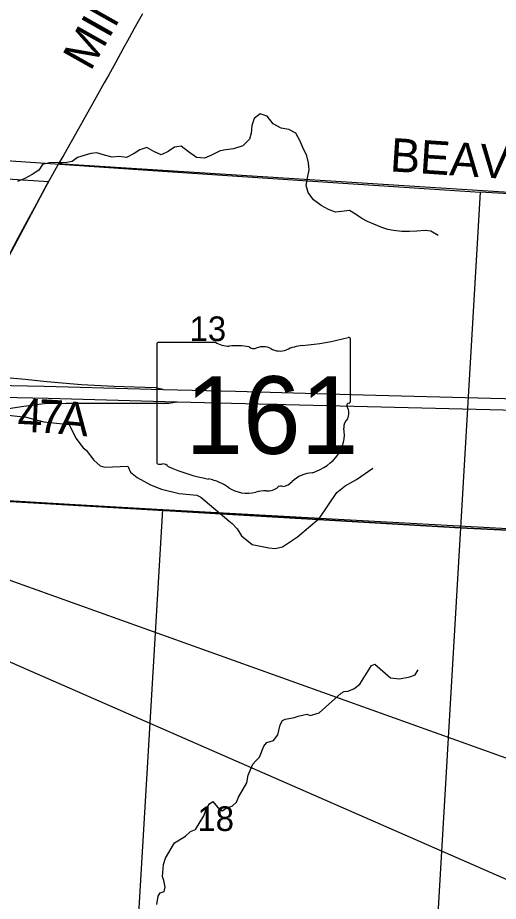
# Model space of a CAD drawing. Extents: x 0 to 91.3, y -0.7 to 22.
# Drawn here: x 7.164 to 7.981, y 16.725 to 18.226 of the extents above; entities that cross this region are included whole.
import ezdxf

# ---------------------------------------------------------------- set-up
doc = ezdxf.new("R2010")
doc.units = 0
for name, color, linetype in [('GM_X_Corporation', 7, 'Continuous'), ('GM_X_County_Road', 7, 'Continuous'), ('GM_X_County_Road_Text', 7, 'Continuous'), ('GM_X_Interchange_Ramps', 7, 'Continuous'), ('GM_X_Major_River', 7, 'Continuous'), ('GM_X_Minor_River', 7, 'Continuous'), ('GM_X_Section_Text', 7, 'Continuous'), ('GM_X_State_Location', 7, 'Continuous'), ('GM_X_State_Route', 7, 'Continuous'), ('GM_X_State_Shield', 7, 'Continuous'), ('GM_X_Township_Road', 7, 'Continuous'), ('GM_X_Township_Road_Text', 7, 'Continuous'), ('SH_Text', 7, 'Continuous')]:
    doc.layers.add(name, color=color, linetype=linetype)

msp = doc.modelspace()

# ---------------------------------------------------------------- linework, layer by layer
at = {"layer": 'GM_X_Corporation'}
for points in [[(6.9448, 17.9966), (7.4187, 17.9645), (7.6912, 17.9463), (7.9506, 17.929), (7.9172, 17.3589), (6.9092, 17.4181)], [(8.9, 17.3103), (8.9, 17.8759), (8.8451, 17.8791), (8.4604, 17.9014), (8.0797, 17.922), (7.9506, 17.929), (7.9172, 17.3589)], [(6.9092, 17.4181), (7.9172, 17.3589), (7.8571, 16.3365), (6.8465, 16.3992)], [(8.9, 16.8754), (8.9, 17.3103), (7.9172, 17.3589), (7.8571, 16.3365), (8.8671, 16.2825)]]:
    msp.add_lwpolyline(points, close=True, dxfattribs=at)
msp.add_lwpolyline([(7.1102, 17.7478), (7.2165, 17.9469), (7.0938, 17.9548)], dxfattribs=at)
at = {"layer": 'GM_X_County_Road'}
for points in [[(7.3765, 18.2324), (7.3618, 18.2063), (7.354, 18.1916), (7.3431, 18.1719), (7.3307, 18.149), (7.3193, 18.1287), (7.3114, 18.1149), (7.2973, 18.0895), (7.2865, 18.0703), (7.2786, 18.0559), (7.2678, 18.0368), (7.2549, 18.0145), (7.2424, 17.9927), (7.2341, 17.9783), (7.2155, 17.9453), (7.2146, 17.9435)], [(7.2146, 17.9435), (7.2058, 17.9273), (7.196, 17.9094), (7.1765, 17.8732)], [(7.1765, 17.8732), (7.176, 17.8723), (7.1653, 17.8521), (7.1576, 17.8379), (7.1385, 17.8015), (7.1283, 17.7822), (7.1245, 17.7751)], [(7.0214, 17.4132), (7.1002, 17.4084), (7.2619, 17.3986), (7.4112, 17.39), (8.3263, 17.3397), (8.5262, 17.3288), (8.8216, 17.3124), (8.9, 17.3095)]]:
    msp.add_lwpolyline(points, dxfattribs=at)
at = {"layer": 'GM_X_Interchange_Ramps'}
for points in [[(7.4118, 17.5942), (7.3985, 17.5971), (7.3279, 17.599), (7.2725, 17.6018), (7.2137, 17.6069), (7.1768, 17.611), (7.0497, 17.6225)], [(7.0157, 17.5554), (7.0325, 17.5545), (7.058, 17.5516), (7.082, 17.5518), (7.103, 17.5537), (7.127, 17.5576), (7.1523, 17.5623), (7.1706, 17.5654), (7.1955, 17.5687), (7.2094, 17.5701), (7.2466, 17.5708), (7.2877, 17.571), (7.4209, 17.5708), (7.4356, 17.5734)]]:
    msp.add_lwpolyline(points, dxfattribs=at)
at = {"layer": 'GM_X_Major_River'}
msp.add_lwpolyline([(7.879, 17.8559), (7.8665, 17.8632), (7.857, 17.864), (7.843, 17.8633), (7.8305, 17.8626), (7.8172, 17.8623), (7.8032, 17.8642), (7.7933, 17.8658), (7.7835, 17.8692), (7.7695, 17.875), (7.7589, 17.8792), (7.749, 17.8845), (7.7384, 17.8921), (7.7282, 17.8979), (7.7146, 17.8964), (7.7047, 17.8953), (7.6926, 17.8999), (7.6801, 17.9064), (7.6669, 17.9163), (7.6578, 17.9285), (7.6545, 17.9406), (7.6568, 17.9535), (7.6599, 17.9671), (7.6584, 17.9789), (7.6558, 17.991), (7.649, 18.0051), (7.6438, 18.0172), (7.637, 18.0294), (7.6253, 18.0355), (7.612, 18.0382), (7.5988, 18.0451), (7.5882, 18.0584), (7.5765, 18.0626), (7.5662, 18.0543), (7.562, 18.0426), (7.5612, 18.0297), (7.5581, 18.0195), (7.5467, 18.0078), (7.5311, 18.0029), (7.5182, 18.001), (7.5084, 17.9996), (7.4939, 17.992), (7.4818, 17.9868), (7.4681, 17.9884), (7.4545, 17.9975), (7.442, 18.0074), (7.431, 18.0056), (7.42, 17.9984), (7.4079, 17.9928), (7.3954, 17.9985), (7.3836, 18.0054), (7.3719, 18.0012), (7.362, 17.9952), (7.3491, 17.9884), (7.337, 17.9896), (7.3248, 17.9889), (7.3119, 17.992), (7.2987, 17.9962), (7.2885, 17.9951), (7.279, 17.9921), (7.2661, 17.988), (7.2566, 17.9816), (7.2448, 17.979), (7.2315, 17.9798), (7.2183, 17.9791), (7.2065, 17.9765), (7.2004, 17.9667), (7.189, 17.9595), (7.1765, 17.9527), (7.1639, 17.9475)], dxfattribs=at)
at = {"layer": 'GM_X_Minor_River'}
for points in [[(7.1379, 17.5517), (7.1784, 17.5473), (7.2087, 17.5392), (7.2519, 17.5347), (7.2628, 17.5112), (7.2756, 17.4951), (7.2808, 17.4909), (7.2936, 17.4738), (7.3046, 17.4643), (7.3125, 17.4623), (7.3516, 17.464), (7.3561, 17.4537), (7.3674, 17.4445), (7.3901, 17.4323), (7.4086, 17.4246), (7.4385, 17.4176), (7.4688, 17.4144), (7.4753, 17.4113), (7.5232, 17.3712), (7.5288, 17.3662), (7.5371, 17.3575), (7.5446, 17.3453), (7.5628, 17.3308), (7.5912, 17.3249), (7.6018, 17.3241), (7.6143, 17.327), (7.6398, 17.3436), (7.6771, 17.3756), (7.7069, 17.4194), (7.721, 17.4307), (7.74, 17.4412), (7.7678, 17.4604)], [(7.5828, 16.9882), (7.5878, 16.9943), (7.5992, 16.998), (7.6064, 17.0074), (7.6107, 17.0245), (7.6142, 17.0317), (7.6191, 17.0343), (7.6347, 17.0368), (7.6411, 17.0391), (7.6555, 17.0428), (7.6616, 17.0405), (7.6768, 17.0449), (7.7141, 17.0781), (7.7194, 17.0811), (7.7255, 17.0818), (7.7358, 17.0859), (7.7461, 17.0938), (7.7659, 17.1255), (7.7713, 17.1274), (7.7981, 17.1041), (7.8132, 17.1029), (7.831, 17.1062), (7.8402, 17.1096), (7.8451, 17.1179)], [(7.4005, 16.7193), (7.4028, 16.7337), (7.4063, 16.7394), (7.4135, 16.7416), (7.415, 16.7485), (7.4125, 16.7602), (7.4102, 16.7671), (7.4122, 16.7875), (7.4157, 16.7981), (7.431, 16.8242), (7.4493, 16.8355), (7.458, 16.8434), (7.4664, 16.8467), (7.4806, 16.8698), (7.4844, 16.8815), (7.4901, 16.8902), (7.4959, 16.8943), (7.5038, 16.8844), (7.5117, 16.8783), (7.5178, 16.8825), (7.5292, 16.8869), (7.5364, 16.893), (7.5395, 16.9017), (7.5537, 16.9262), (7.556, 16.9391), (7.5637, 16.9576), (7.5683, 16.9629), (7.5751, 16.9697), (7.5828, 16.9882)]]:
    msp.add_lwpolyline(points, dxfattribs=at)
at = {"layer": 'GM_X_State_Route'}
for points in [[(6.4147, 17.6193), (6.5219, 17.6168), (6.6723, 17.6131), (6.6849, 17.6128), (6.8294, 17.6094), (6.884, 17.6079), (7.0398, 17.6034), (7.2094, 17.5996), (7.3717, 17.5953), (7.4118, 17.5942), (7.5344, 17.5911), (7.7514, 17.5852), (7.9683, 17.5793), (8.1766, 17.5745), (8.2816, 17.5714), (8.4129, 17.5685), (8.5578, 17.5648), (8.7192, 17.5607), (8.864, 17.5567), (8.9, 17.5553)], [(6.4159, 17.5998), (6.677, 17.5931), (6.7472, 17.5914), (6.8769, 17.5882), (7.0303, 17.5836), (7.2161, 17.5792), (7.4145, 17.5739), (7.4356, 17.5734), (8.0357, 17.5587), (8.843, 17.5339), (8.9, 17.5321)]]:
    msp.add_lwpolyline(points, dxfattribs=at)
at = {"layer": 'GM_X_State_Shield'}
for p, q in [((7.4005, 17.6708), (7.4005, 17.4707)), ((7.5003, 17.6742), (7.4037, 17.6742)), ((7.7301, 17.5745), (7.7301, 17.6792)), ((7.73, 17.5745), (7.7301, 17.5745))]:
    msp.add_line(p, q, dxfattribs=at)
for centre, major_axis, start_param, end_param in [((7.6127, 17.9471), (0.3495, 0), 4.814394, 5.042369), ((7.7264, 17.6796), (0.00367, 0), 6.141152, 7.989035), ((7.4043, 17.6712), (0.00382, 0), 1.712693, 3.28349), ((7.5232, 17.6975), (0.037, 0), 4.042523, 4.731795), ((7.5355, 17.5619), (0.133, 0), 1.404758, 1.657858), ((7.5657, 17.6722), (0.0107, 0), 3.836095, 5.185415), ((7.5814, 17.6491), (0.0222, 0), 0.950623, 2.079405), ((7.6572, 17.6131), (0.0703, 0), 1.699011, 2.107814), ((7.6101, 17.6808), (0.0267, 0), 4.081561, 5.145723), ((7.7292, 17.5668), (0.00568, 0), 1.883978, 3.671073), ((7.6931, 17.5536), (0.0341, 0), 5.934695, 6.695948), ((7.7262, 17.5741), (0.00393, 0), 5.05454, 6.418171), ((7.7432, 17.5307), (0.0248, 0), 2.387724, 3.262537), ((7.6322, 17.5174), (0.0874, 0), 5.101752, 6.440018), ((7.4043, 17.4702), (0.00385, 0), 3.00124, 4.508301), ((7.4049, 17.4907), (0.0294, 0), 4.665946, 4.897461), ((7.4109, 17.4591), (0.0106, 0), 0.519207, 1.627899), ((7.5447, 17.6389), (0.2524, 0), 4.195997, 4.488961), ((7.4695, 17.3808), (0.079, 0), 0.823519, 1.323587), ((7.6691, 17.4145), (0.0479, 0), 1.647645, 2.488434), ((7.5549, 17.4581), (0.0501, 0), 4.026481, 4.996735), ((7.5875, 17.4431), (0.0267, 0), 4.691044, 5.507374), ((7.6116, 17.4238), (0.00752, 0), 1.147584, 2.315152), ((7.6084, 17.4513), (0.0282, 0), 4.937069, 5.64225), ((7.5838, 17.3889), (0.0412, 0), 1.495662, 1.94098)]:
    msp.add_ellipse(centre, major_axis=major_axis, ratio=0.8, start_param=start_param, end_param=end_param, dxfattribs=at)
at = {"layer": 'GM_X_Township_Road'}
for points in [[(8.847, 17.875), (7.2414, 17.9769), (7.2341, 17.9783)], [(7.3114, 15.6975), (7.3131, 15.8164), (7.3495, 16.3603), (7.4112, 17.39)]]:
    msp.add_lwpolyline(points, dxfattribs=at)
at = {"layer": 'SH_Text'}
msp.add_lwpolyline([(9.2012, 16.2343), (5.4038, 17.8952), (9.2012, 16.5366)], close=True, dxfattribs=at)

# ---------------------------------------------------------------- texts
at = {"layer": 'GM_X_County_Road_Text'}
msp.add_text('MINK', height=0.05682, rotation=60.6284, dxfattribs=at).set_placement((7.2881, 18.1334))
at = {"layer": 'GM_X_Section_Text'}
for s, p in [('13', (7.4564, 17.6763)), ('18', (7.4697, 16.8442))]:
    msp.add_text(s, height=0.04186, rotation=0, dxfattribs=at).set_placement(p)
at = {"layer": 'GM_X_State_Location'}
for s in ['s', 'r']:
    msp.add_text(s, height=0.000189, dxfattribs=at).set_placement((7.5616, 17.5574))
msp.add_text('161', height=0.000189, rotation=0, dxfattribs=at).set_placement((7.4947, 17.5436))
at = {"layer": 'GM_X_State_Shield'}
msp.add_text('161', height=0.13184, dxfattribs=at).set_placement((7.4491, 17.4848))
at = {"layer": 'GM_X_Township_Road_Text'}
for s, height, rotation, p in [('BEAVER', 0.05682, 356.2203, (7.7962, 17.9648)), ('4', 0.0568, 357.1732, (7.1631, 17.5229)), ('7', 0.0568, 356.412, (7.1979, 17.5212)), ('A', 0.0568, 354.7178, (7.2323, 17.519))]:
    msp.add_text(s, height=height, rotation=rotation, dxfattribs=at).set_placement(p)

doc.saveas('drawing.dxf')
